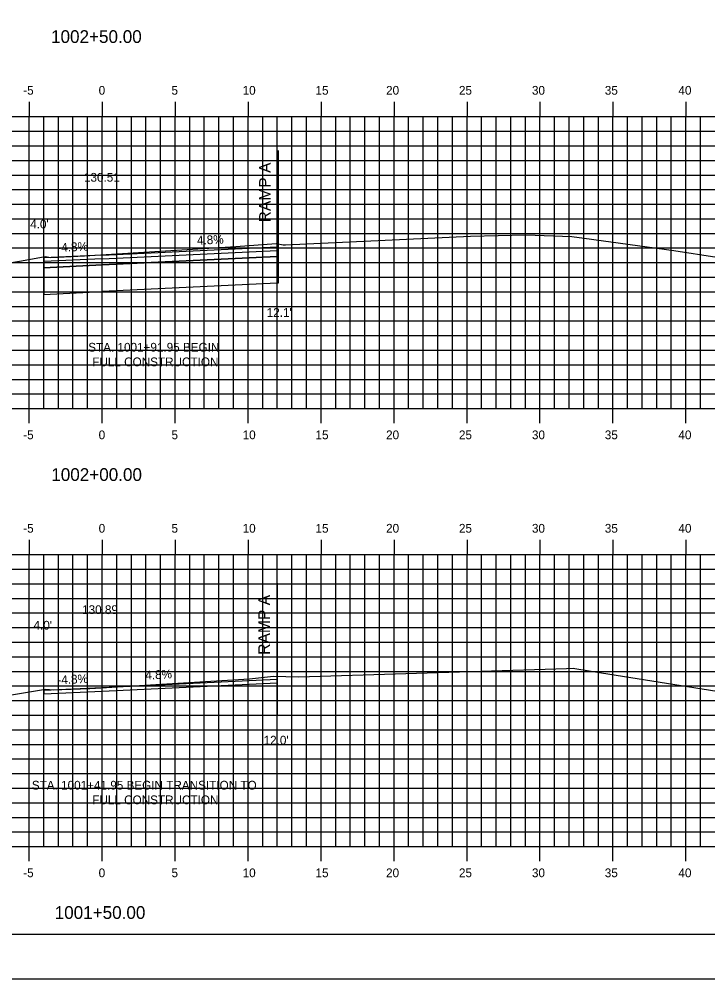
# Model space of a CAD drawing. Extents: x 850851 to 851023, y 365624 to 365734.
# Drawn here: x 850928.8 to 850976, y 365624 to 365689.7 of the extents above; entities that cross this region are included whole.
import ezdxf

# ---------------------------------------------------------------- set-up
doc = ezdxf.new("R2010")
doc.units = 0
for name, color, linetype in [('ANNOTATION', 7, 'Continuous'), ('BORDER', 7, 'Continuous'), ('D_Roadway_Centerline', 7, 'Continuous'), ('D_Roadway_Centerline_Text', 7, 'Continuous'), ('D_Roadway_Edge_Shoulder', 7, 'Continuous'), ('D_Roadway_Edge_TW', 7, 'Continuous'), ('D_Roadway_Pavement', 7, 'Continuous'), ('D_Roadway_SubGrade', 7, 'Continuous'), ('D_Text_Standard', 7, 'Continuous'), ('H_V ANNOTATION', 7, 'Continuous'), ('M_Roadway_Centerline', 7, 'Continuous'), ('MAJOR', 7, 'Continuous'), ('MINOR', 7, 'Continuous'), ('PLOT BOUNDARY', 7, 'Continuous'), ('S_Roadway_Centerline', 7, 'Continuous')]:
    doc.layers.add(name, color=color, linetype=linetype)

msp = doc.modelspace()

# ---------------------------------------------------------------- linework, layer by layer
at = {"layer": 'BORDER'}
msp.add_lwpolyline([(850859.496, 365627.027), (851019.496, 365627.027), (851019.496, 365732.027), (850859.496, 365732.027)], close=True, dxfattribs=at)
at = {"layer": 'D_Roadway_Edge_Shoulder'}
for p, q in [((850946.496, 365674.112), (850946.494, 365673.862)), ((850934.494, 365643.671), (850946.497, 365644.247))]:
    msp.add_line(p, q, dxfattribs=at)
for points in [[(850934.496, 365673.536), (850946.496, 365674.112), (850946.557, 365674.115)], [(850934.494, 365673.286), (850934.496, 365673.536), (850930.494, 365673.344)], [(850930.496, 365643.729), (850934.496, 365643.921), (850946.496, 365644.497)], [(850930.496, 365643.729), (850930.494, 365643.479), (850934.494, 365643.671), (850934.496, 365643.671), (850934.496, 365643.921)]]:
    msp.add_lwpolyline(points, dxfattribs=at)
at = {"layer": 'D_Roadway_Edge_TW'}
msp.add_lwpolyline([(850946.496, 365644.497), (850946.497, 365644.497), (850946.497, 365644.331), (850946.496, 365644.331)], close=True, dxfattribs=at)
at = {"layer": 'D_Roadway_Pavement'}
for points in [[(850934.494, 365673.286), (850946.494, 365673.862), (850946.494, 365673.445), (850934.494, 365672.869)], [(850934.494, 365673.286), (850930.494, 365673.094), (850930.494, 365672.677), (850934.494, 365672.869)]]:
    msp.add_lwpolyline(points, close=True, dxfattribs=at)
for points in [[(850946.557, 365673.448), (850946.494, 365673.445), (850946.494, 365673.862), (850946.557, 365673.865)], [(850946.497, 365643.83), (850946.494, 365643.83), (850946.494, 365644.247), (850946.497, 365644.247)]]:
    msp.add_lwpolyline(points, dxfattribs=at)
at = {"layer": 'D_Roadway_SubGrade'}
for p, q in [((850946.557, 365680.695), (850946.557, 365673.948)), ((850946.557, 365673.948), (850946.557, 365671.615)), ((850946.497, 365651.078), (850946.497, 365644.331)), ((850946.497, 365644.331), (850946.497, 365641.997))]:
    msp.add_line(p, q, dxfattribs=at)
for points in [[(850934.494, 365672.869), (850946.494, 365673.445), (850946.494, 365671.612), (850934.494, 365671.036)], [(850934.494, 365672.869), (850930.494, 365672.677), (850930.494, 365673.177), (850930.494, 365673.344), (850930.494, 365670.844), (850934.494, 365671.036)]]:
    msp.add_lwpolyline(points, close=True, dxfattribs=at)
for points in [[(850946.557, 365671.615), (850946.494, 365671.612), (850946.494, 365673.445), (850946.557, 365673.448)], [(850946.497, 365641.997), (850946.494, 365641.997), (850946.494, 365643.83), (850946.497, 365643.83)]]:
    msp.add_lwpolyline(points, dxfattribs=at)
at = {"layer": 'MAJOR'}
for p, q in [((850929.496, 365684.029), (850929.496, 365683.027)), ((850934.496, 365684.029), (850934.496, 365683.027)), ((850939.496, 365684.029), (850939.496, 365683.027)), ((850944.496, 365684.029), (850944.496, 365683.027)), ((850949.496, 365684.029), (850949.496, 365683.027)), ((850954.496, 365684.029), (850954.496, 365683.027)), ((850959.496, 365684.029), (850959.496, 365683.027)), ((850964.496, 365684.029), (850964.496, 365683.027)), ((850969.496, 365684.029), (850969.496, 365683.027)), ((850974.496, 365684.029), (850974.496, 365683.027)), ((850864.496, 365683.027), (851004.496, 365683.027)), ((850864.496, 365683.027), (851004.496, 365683.027)), ((850929.496, 365663.027), (850929.496, 365683.027)), ((850934.496, 365663.027), (850934.496, 365683.027)), ((850939.496, 365663.027), (850939.496, 365683.027)), ((850944.496, 365663.027), (850944.496, 365683.027)), ((850949.496, 365663.027), (850949.496, 365683.027)), ((850954.496, 365663.027), (850954.496, 365683.027)), ((850959.496, 365663.027), (850959.496, 365683.027)), ((850964.496, 365663.027), (850964.496, 365683.027)), ((850969.496, 365663.027), (850969.496, 365683.027)), ((850974.496, 365663.027), (850974.496, 365683.027)), ((850864.496, 365678.027), (851004.496, 365678.027)), ((850864.496, 365673.027), (851004.496, 365673.027)), ((850864.496, 365668.027), (851004.496, 365668.027)), ((850864.496, 365663.027), (851004.496, 365663.027)), ((850864.496, 365663.027), (851004.496, 365663.027)), ((850929.496, 365662.025), (850929.496, 365663.027)), ((850934.496, 365662.025), (850934.496, 365663.027)), ((850939.496, 365662.025), (850939.496, 365663.027)), ((850944.496, 365662.025), (850944.496, 365663.027)), ((850949.496, 365662.025), (850949.496, 365663.027)), ((850954.496, 365662.025), (850954.496, 365663.027)), ((850959.496, 365662.025), (850959.496, 365663.027)), ((850964.496, 365662.025), (850964.496, 365663.027)), ((850969.496, 365662.025), (850969.496, 365663.027)), ((850974.496, 365662.025), (850974.496, 365663.027)), ((850929.496, 365654.029), (850929.496, 365653.027)), ((850934.496, 365654.029), (850934.496, 365653.027)), ((850939.496, 365654.029), (850939.496, 365653.027)), ((850944.496, 365654.029), (850944.496, 365653.027)), ((850949.496, 365654.029), (850949.496, 365653.027)), ((850954.496, 365654.029), (850954.496, 365653.027)), ((850959.496, 365654.029), (850959.496, 365653.027)), ((850964.496, 365654.029), (850964.496, 365653.027)), ((850969.496, 365654.029), (850969.496, 365653.027)), ((850974.496, 365654.029), (850974.496, 365653.027)), ((850864.496, 365653.027), (851004.496, 365653.027)), ((850864.496, 365653.027), (851004.496, 365653.027)), ((850929.496, 365633.027), (850929.496, 365653.027)), ((850934.496, 365633.027), (850934.496, 365653.027)), ((850939.496, 365633.027), (850939.496, 365653.027)), ((850944.496, 365633.027), (850944.496, 365653.027)), ((850949.496, 365633.027), (850949.496, 365653.027)), ((850954.496, 365633.027), (850954.496, 365653.027)), ((850959.496, 365633.027), (850959.496, 365653.027)), ((850964.496, 365633.027), (850964.496, 365653.027)), ((850969.496, 365633.027), (850969.496, 365653.027)), ((850974.496, 365633.027), (850974.496, 365653.027)), ((850864.496, 365648.027), (851004.496, 365648.027)), ((850864.496, 365643.027), (851004.496, 365643.027)), ((850864.496, 365638.027), (851004.496, 365638.027)), ((850864.496, 365633.027), (851004.496, 365633.027)), ((850864.496, 365633.027), (851004.496, 365633.027)), ((850929.496, 365632.025), (850929.496, 365633.027)), ((850934.496, 365632.025), (850934.496, 365633.027)), ((850939.496, 365632.025), (850939.496, 365633.027)), ((850944.496, 365632.025), (850944.496, 365633.027)), ((850949.496, 365632.025), (850949.496, 365633.027)), ((850954.496, 365632.025), (850954.496, 365633.027)), ((850959.496, 365632.025), (850959.496, 365633.027)), ((850964.496, 365632.025), (850964.496, 365633.027)), ((850969.496, 365632.025), (850969.496, 365633.027)), ((850974.496, 365632.025), (850974.496, 365633.027))]:
    msp.add_line(p, q, dxfattribs=at)
at = {"layer": 'MINOR'}
for p, q in [((850930.496, 365663.027), (850930.496, 365683.027)), ((850931.496, 365663.027), (850931.496, 365683.027)), ((850932.496, 365663.027), (850932.496, 365683.027)), ((850933.496, 365663.027), (850933.496, 365683.027)), ((850935.496, 365663.027), (850935.496, 365683.027)), ((850936.496, 365663.027), (850936.496, 365683.027)), ((850937.496, 365663.027), (850937.496, 365683.027)), ((850938.496, 365663.027), (850938.496, 365683.027)), ((850940.496, 365663.027), (850940.496, 365683.027)), ((850941.496, 365663.027), (850941.496, 365683.027)), ((850942.496, 365663.027), (850942.496, 365683.027)), ((850943.496, 365663.027), (850943.496, 365683.027)), ((850945.496, 365663.027), (850945.496, 365683.027)), ((850946.496, 365663.027), (850946.496, 365683.027)), ((850947.496, 365663.027), (850947.496, 365683.027)), ((850948.496, 365663.027), (850948.496, 365683.027)), ((850950.496, 365663.027), (850950.496, 365683.027)), ((850951.496, 365663.027), (850951.496, 365683.027)), ((850952.496, 365663.027), (850952.496, 365683.027)), ((850953.496, 365663.027), (850953.496, 365683.027)), ((850955.496, 365663.027), (850955.496, 365683.027)), ((850956.496, 365663.027), (850956.496, 365683.027)), ((850957.496, 365663.027), (850957.496, 365683.027)), ((850958.496, 365663.027), (850958.496, 365683.027)), ((850960.496, 365663.027), (850960.496, 365683.027)), ((850961.496, 365663.027), (850961.496, 365683.027)), ((850962.496, 365663.027), (850962.496, 365683.027)), ((850963.496, 365663.027), (850963.496, 365683.027)), ((850965.496, 365663.027), (850965.496, 365683.027)), ((850966.496, 365663.027), (850966.496, 365683.027)), ((850967.496, 365663.027), (850967.496, 365683.027)), ((850968.496, 365663.027), (850968.496, 365683.027)), ((850970.496, 365663.027), (850970.496, 365683.027)), ((850971.496, 365663.027), (850971.496, 365683.027)), ((850972.496, 365663.027), (850972.496, 365683.027)), ((850973.496, 365663.027), (850973.496, 365683.027)), ((850975.496, 365663.027), (850975.496, 365683.027)), ((850864.496, 365682.027), (851004.496, 365682.027)), ((850864.496, 365681.027), (851004.496, 365681.027)), ((850864.496, 365680.027), (851004.496, 365680.027)), ((850864.496, 365679.027), (851004.496, 365679.027)), ((850864.496, 365677.027), (851004.496, 365677.027)), ((850864.496, 365676.027), (851004.496, 365676.027)), ((850864.496, 365675.027), (851004.496, 365675.027)), ((850864.496, 365674.027), (851004.496, 365674.027)), ((850864.496, 365672.027), (851004.496, 365672.027)), ((850864.496, 365671.027), (851004.496, 365671.027)), ((850864.496, 365670.027), (851004.496, 365670.027)), ((850864.496, 365669.027), (851004.496, 365669.027)), ((850864.496, 365667.027), (851004.496, 365667.027)), ((850864.496, 365666.027), (851004.496, 365666.027)), ((850864.496, 365665.027), (851004.496, 365665.027)), ((850864.496, 365664.027), (851004.496, 365664.027)), ((850930.496, 365633.027), (850930.496, 365653.027)), ((850931.496, 365633.027), (850931.496, 365653.027)), ((850932.496, 365633.027), (850932.496, 365653.027)), ((850933.496, 365633.027), (850933.496, 365653.027)), ((850935.496, 365633.027), (850935.496, 365653.027)), ((850936.496, 365633.027), (850936.496, 365653.027)), ((850937.496, 365633.027), (850937.496, 365653.027)), ((850938.496, 365633.027), (850938.496, 365653.027)), ((850940.496, 365633.027), (850940.496, 365653.027)), ((850941.496, 365633.027), (850941.496, 365653.027)), ((850942.496, 365633.027), (850942.496, 365653.027)), ((850943.496, 365633.027), (850943.496, 365653.027)), ((850945.496, 365633.027), (850945.496, 365653.027)), ((850946.496, 365633.027), (850946.496, 365653.027)), ((850947.496, 365633.027), (850947.496, 365653.027)), ((850948.496, 365633.027), (850948.496, 365653.027)), ((850950.496, 365633.027), (850950.496, 365653.027)), ((850951.496, 365633.027), (850951.496, 365653.027)), ((850952.496, 365633.027), (850952.496, 365653.027)), ((850953.496, 365633.027), (850953.496, 365653.027)), ((850955.496, 365633.027), (850955.496, 365653.027)), ((850956.496, 365633.027), (850956.496, 365653.027)), ((850957.496, 365633.027), (850957.496, 365653.027)), ((850958.496, 365633.027), (850958.496, 365653.027)), ((850960.496, 365633.027), (850960.496, 365653.027)), ((850961.496, 365633.027), (850961.496, 365653.027)), ((850962.496, 365633.027), (850962.496, 365653.027)), ((850963.496, 365633.027), (850963.496, 365653.027)), ((850965.496, 365633.027), (850965.496, 365653.027)), ((850966.496, 365633.027), (850966.496, 365653.027)), ((850967.496, 365633.027), (850967.496, 365653.027)), ((850968.496, 365633.027), (850968.496, 365653.027)), ((850970.496, 365633.027), (850970.496, 365653.027)), ((850971.496, 365633.027), (850971.496, 365653.027)), ((850972.496, 365633.027), (850972.496, 365653.027)), ((850973.496, 365633.027), (850973.496, 365653.027)), ((850975.496, 365633.027), (850975.496, 365653.027)), ((850864.496, 365652.027), (851004.496, 365652.027)), ((850864.496, 365651.027), (851004.496, 365651.027)), ((850864.496, 365650.027), (851004.496, 365650.027)), ((850864.496, 365649.027), (851004.496, 365649.027)), ((850864.496, 365647.027), (851004.496, 365647.027)), ((850864.496, 365646.027), (851004.496, 365646.027)), ((850864.496, 365645.027), (851004.496, 365645.027)), ((850864.496, 365644.027), (851004.496, 365644.027)), ((850864.496, 365642.027), (851004.496, 365642.027)), ((850864.496, 365641.027), (851004.496, 365641.027)), ((850864.496, 365640.027), (851004.496, 365640.027)), ((850864.496, 365639.027), (851004.496, 365639.027)), ((850864.496, 365637.027), (851004.496, 365637.027)), ((850864.496, 365636.027), (851004.496, 365636.027)), ((850864.496, 365635.027), (851004.496, 365635.027)), ((850864.496, 365634.027), (851004.496, 365634.027))]:
    msp.add_line(p, q, dxfattribs=at)
at = {"layer": 'PLOT BOUNDARY'}
msp.add_lwpolyline([(850851.403, 365623.968), (851021.403, 365623.968), (851021.403, 365733.968), (850851.403, 365733.968)], close=True, dxfattribs=at)
at = {"layer": 'S_Roadway_Centerline'}
for points in [[(850917.187, 365671.156), (850928.976, 365673.159), (850930.6, 365673.434), (850930.974, 365673.369), (850933.274, 365673.491), (850943.657, 365674.123), (850946.409, 365674.339), (850946.89, 365674.241), (850947.06, 365674.249), (850959.735, 365674.832), (850963.529, 365674.924), (850966.679, 365674.819), (850967.512, 365674.708), (850973.662, 365673.86), (850982.515, 365672.487), (850999.367, 365669.418), (850999.593, 365669.377), (850999.701, 365669.367), (851003.131, 365669.253), (851004.496, 365669.757)], [(850927.869, 365643.356), (850930.484, 365643.789), (850930.631, 365643.818), (850931.158, 365643.765), (850931.729, 365643.789), (850933.655, 365643.859), (850944.6, 365644.522), (850946.236, 365644.691), (850947.929, 365644.648), (850948.697, 365644.668), (850966.304, 365645.223), (850966.771, 365645.236), (850966.888, 365645.217), (850968.7, 365644.924), (850984.525, 365642.416), (850998.292, 365640.256), (851000.356, 365639.969), (851001.414, 365639.96), (851002.897, 365639.934), (851004.086, 365640.301), (851004.496, 365640.427)]]:
    msp.add_lwpolyline(points, dxfattribs=at)

# ---------------------------------------------------------------- texts
at = {"layer": 'ANNOTATION'}
for s, height, rotation, p in [('RAMP A', 0.8, 90, (850946.05, 365675.779)), ('4.8%', 0.6, 2.74807, (850941.006, 365674.249)), ('-4.8%', 0.6, 2.74806, (850931.44, 365673.751)), ('RAMP A', 0.8, 90, (850945.99, 365646.162)), ('4.8%', 0.6, 2.74817, (850937.464, 365644.464)), ('-4.8%', 0.6, 2.74806, (850931.442, 365644.136))]:
    msp.add_text(s, height=height, rotation=rotation, dxfattribs=at).set_placement(p)
for s, p in [('STA. 1001+91.95 BEGIN', (850933.54, 365666.928)), ('FULL CONSTRUCTION', (850933.815, 365665.926)), ('STA. 1001+41.95 BEGIN TRANSITION TO', (850929.676, 365636.928)), ('FULL CONSTRUCTION', (850933.815, 365635.926))]:
    msp.add_text(s, height=0.6, dxfattribs=at).set_placement(p)
at = {"layer": 'D_Roadway_Centerline'}
for s, p in [('C', (850934.491, 365673.536)), ('L', (850934.496, 365673.528)), ('C', (850934.49, 365643.921)), ('L', (850934.496, 365643.913))]:
    msp.add_text(s, height=0.0146, dxfattribs=at).set_placement(p)
at = {"layer": 'D_Roadway_Centerline_Text'}
for s, p in [('130.51', (850933.249, 365678.568)), ('130.89', (850933.121, 365648.953))]:
    msp.add_text(s, height=0.6, dxfattribs=at).set_placement(p)
at = {"layer": 'D_Text_Standard'}
for s, p in [("4.0'", (850929.562, 365675.367)), ("12.1'", (850945.768, 365669.311)), ("4.0'", (850929.79, 365647.886)), ("12.0'", (850945.558, 365640.013))]:
    msp.add_text(s, height=0.6, dxfattribs=at).set_placement(p)
at = {"layer": 'H_V ANNOTATION'}
for s, height, p in [('1002+50.00', 0.875, (850930.992, 365688.07)), ('-5', 0.6, (850929.087, 365684.527)), ('0', 0.6, (850934.255, 365684.527)), ('5', 0.6, (850939.247, 365684.527)), ('10', 0.6, (850944.121, 365684.527)), ('15', 0.6, (850949.113, 365684.527)), ('20', 0.6, (850953.95, 365684.527)), ('25', 0.6, (850958.942, 365684.527)), ('30', 0.6, (850963.945, 365684.527)), ('35', 0.6, (850968.937, 365684.527)), ('40', 0.6, (850973.982, 365684.527)), ('-5', 0.6, (850929.087, 365660.927)), ('0', 0.6, (850934.255, 365660.927)), ('5', 0.6, (850939.247, 365660.927)), ('10', 0.6, (850944.121, 365660.927)), ('15', 0.6, (850949.113, 365660.927)), ('20', 0.6, (850953.95, 365660.927)), ('25', 0.6, (850958.942, 365660.927)), ('30', 0.6, (850963.945, 365660.927)), ('35', 0.6, (850968.937, 365660.927)), ('40', 0.6, (850973.982, 365660.927)), ('1002+00.00', 0.875, (850931.008, 365658.07)), ('-5', 0.6, (850929.087, 365654.527)), ('0', 0.6, (850934.255, 365654.527)), ('5', 0.6, (850939.247, 365654.527)), ('10', 0.6, (850944.121, 365654.527)), ('15', 0.6, (850949.113, 365654.527)), ('20', 0.6, (850953.95, 365654.527)), ('25', 0.6, (850958.942, 365654.527)), ('30', 0.6, (850963.945, 365654.527)), ('35', 0.6, (850968.937, 365654.527)), ('40', 0.6, (850973.982, 365654.527)), ('-5', 0.6, (850929.087, 365630.927)), ('0', 0.6, (850934.255, 365630.927)), ('5', 0.6, (850939.247, 365630.927)), ('10', 0.6, (850944.121, 365630.927)), ('15', 0.6, (850949.113, 365630.927)), ('20', 0.6, (850953.95, 365630.927)), ('25', 0.6, (850958.942, 365630.927)), ('30', 0.6, (850963.945, 365630.927)), ('35', 0.6, (850968.937, 365630.927)), ('40', 0.6, (850973.982, 365630.927)), ('1001+50.00', 0.875, (850931.242, 365628.07))]:
    msp.add_text(s, height=height, dxfattribs=at).set_placement(p)
at = {"layer": 'M_Roadway_Centerline'}
for s, p in [('C', (850946.404, 365674.339)), ('L', (850946.409, 365674.331)), ('C', (850946.23, 365644.691)), ('L', (850946.236, 365644.684))]:
    msp.add_text(s, height=0.0146, dxfattribs=at).set_placement(p)

doc.saveas('drawing.dxf')
